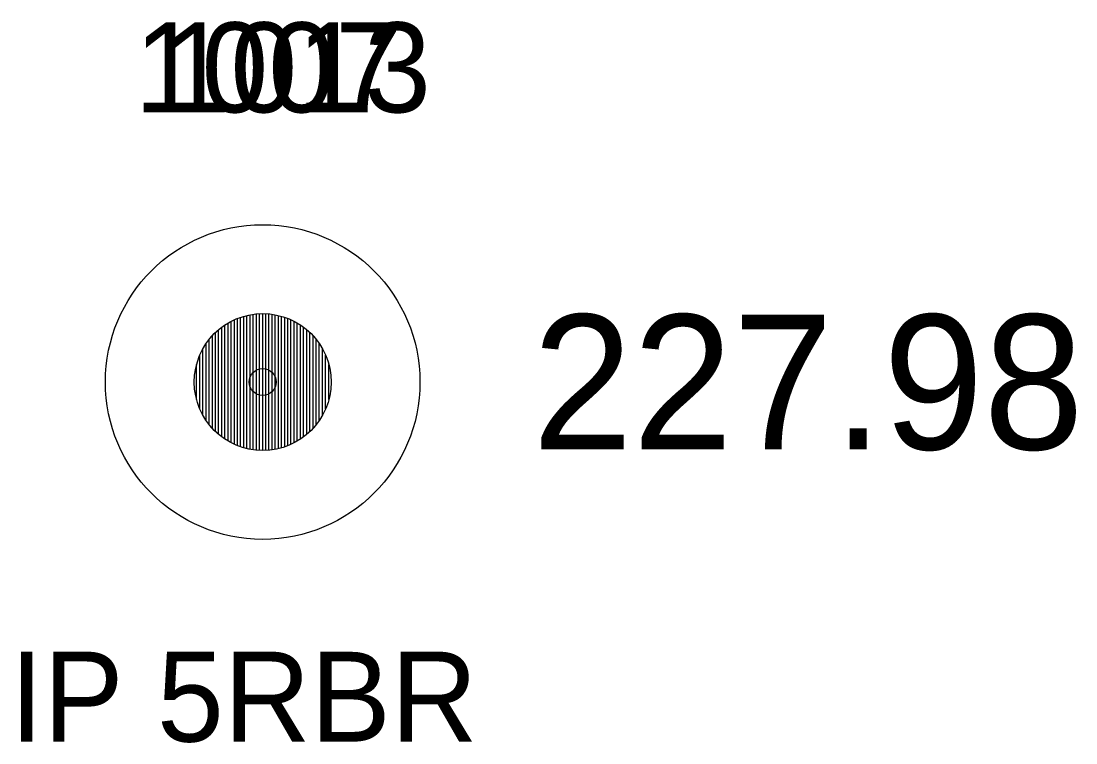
# Model space of a CAD drawing. Extents: x 1961231 to 1962574, y 799865 to 801120.
# Drawn here: x 1962434.89 to 1962446.63, y 799889.64 to 799897.66 of the extents above; entities that cross this region are included whole.
import ezdxf

# ---------------------------------------------------------------- set-up
doc = ezdxf.new("R2010")
doc.units = 0
for name, color, linetype in [('RD_EX_DV_Prop_txCode', 7, 'Continuous'), ('RD_EX_DV_PropPin', 7, 'Continuous'), ('RD_EX_TX_DV_Prop_ELEV', 7, 'Continuous'), ('RD_SMD_Locator', 7, 'Continuous')]:
    doc.layers.add(name, color=color, linetype=linetype)

msp = doc.modelspace()

# ---------------------------------------------------------------- linework, layer by layer
at = {"layer": 'RD_EX_DV_PropPin'}
for p, q in [((1962437.229, 799892.974), (1962437.229, 799894.326)), ((1962437.229, 799892.974), (1962437.229, 799894.326)), ((1962437.264, 799892.957), (1962437.264, 799894.343)), ((1962437.264, 799892.957), (1962437.264, 799894.343)), ((1962437.299, 799892.942), (1962437.299, 799894.358)), ((1962437.299, 799892.942), (1962437.299, 799894.358)), ((1962437.334, 799892.93), (1962437.334, 799894.37)), ((1962437.334, 799892.93), (1962437.334, 799894.37)), ((1962437.369, 799892.919), (1962437.369, 799894.381)), ((1962437.369, 799892.919), (1962437.369, 799894.381)), ((1962437.404, 799892.909), (1962437.404, 799894.391)), ((1962437.404, 799892.909), (1962437.404, 799894.391)), ((1962437.439, 799892.902), (1962437.439, 799894.398)), ((1962437.439, 799892.902), (1962437.439, 799894.398)), ((1962437.474, 799892.896), (1962437.474, 799894.404)), ((1962437.474, 799892.896), (1962437.474, 799894.404)), ((1962437.509, 799892.892), (1962437.509, 799894.408)), ((1962437.509, 799892.892), (1962437.509, 799894.408)), ((1962437.544, 799892.89), (1962437.544, 799894.41)), ((1962437.544, 799892.89), (1962437.544, 799894.41)), ((1962437.579, 799892.889), (1962437.579, 799894.411)), ((1962437.579, 799892.889), (1962437.579, 799894.411)), ((1962437.614, 799892.89), (1962437.614, 799894.41)), ((1962437.614, 799892.89), (1962437.614, 799894.41)), ((1962437.649, 799892.892), (1962437.649, 799894.408)), ((1962437.649, 799892.892), (1962437.649, 799894.408)), ((1962437.684, 799892.896), (1962437.684, 799894.404)), ((1962437.684, 799892.896), (1962437.684, 799894.404)), ((1962437.719, 799892.902), (1962437.719, 799894.398)), ((1962437.719, 799892.902), (1962437.719, 799894.398)), ((1962437.754, 799892.909), (1962437.754, 799894.391)), ((1962437.754, 799892.909), (1962437.754, 799894.391)), ((1962437.789, 799892.919), (1962437.789, 799894.381)), ((1962437.789, 799892.919), (1962437.789, 799894.381)), ((1962437.824, 799892.93), (1962437.824, 799894.37)), ((1962437.824, 799892.93), (1962437.824, 799894.37)), ((1962437.859, 799892.942), (1962437.859, 799894.358)), ((1962437.859, 799892.942), (1962437.859, 799894.358)), ((1962437.894, 799892.957), (1962437.894, 799894.343)), ((1962437.894, 799892.957), (1962437.894, 799894.343)), ((1962437.929, 799892.974), (1962437.929, 799894.326)), ((1962437.929, 799892.974), (1962437.929, 799894.326)), ((1962437.089, 799893.068), (1962437.089, 799894.232)), ((1962437.089, 799893.068), (1962437.089, 799894.232)), ((1962437.124, 799893.04), (1962437.124, 799894.26)), ((1962437.124, 799893.04), (1962437.124, 799894.26)), ((1962437.159, 799893.015), (1962437.159, 799894.285)), ((1962437.159, 799893.015), (1962437.159, 799894.285)), ((1962437.194, 799892.994), (1962437.194, 799894.306)), ((1962437.194, 799892.994), (1962437.194, 799894.306)), ((1962437.964, 799892.994), (1962437.964, 799894.306)), ((1962437.964, 799892.994), (1962437.964, 799894.306)), ((1962437.999, 799893.015), (1962437.999, 799894.285)), ((1962437.999, 799893.015), (1962437.999, 799894.285)), ((1962438.034, 799893.04), (1962438.034, 799894.26)), ((1962438.034, 799893.04), (1962438.034, 799894.26)), ((1962438.069, 799893.068), (1962438.069, 799894.232)), ((1962438.069, 799893.068), (1962438.069, 799894.232)), ((1962436.984, 799893.176), (1962436.984, 799894.124)), ((1962436.984, 799893.176), (1962436.984, 799894.124)), ((1962437.019, 799893.135), (1962437.019, 799894.165)), ((1962437.019, 799893.135), (1962437.019, 799894.165)), ((1962437.054, 799893.099), (1962437.054, 799894.201)), ((1962437.054, 799893.099), (1962437.054, 799894.201)), ((1962438.104, 799893.099), (1962438.104, 799894.201)), ((1962438.104, 799893.099), (1962438.104, 799894.201)), ((1962438.139, 799893.135), (1962438.139, 799894.165)), ((1962438.139, 799893.135), (1962438.139, 799894.165)), ((1962438.174, 799893.176), (1962438.174, 799894.124)), ((1962438.174, 799893.176), (1962438.174, 799894.124)), ((1962436.914, 799893.28), (1962436.914, 799894.02)), ((1962436.914, 799893.28), (1962436.914, 799894.02)), ((1962436.949, 799893.223), (1962436.949, 799894.077)), ((1962436.949, 799893.223), (1962436.949, 799894.077)), ((1962438.209, 799893.223), (1962438.209, 799894.077)), ((1962438.209, 799893.223), (1962438.209, 799894.077)), ((1962438.244, 799893.28), (1962438.244, 799894.02)), ((1962438.244, 799893.28), (1962438.244, 799894.02)), ((1962436.878, 799893.352), (1962436.878, 799893.948)), ((1962436.878, 799893.352), (1962436.878, 799893.948)), ((1962438.279, 799893.352), (1962438.279, 799893.948)), ((1962438.279, 799893.352), (1962438.279, 799893.948)), ((1962436.843, 799893.454), (1962436.843, 799893.846)), ((1962436.843, 799893.454), (1962436.843, 799893.846)), ((1962438.314, 799893.454), (1962438.314, 799893.846)), ((1962438.314, 799893.454), (1962438.314, 799893.846))]:
    msp.add_line(p, q, dxfattribs=at)
for radius in [1.75, 1.75, 0.761, 0.761]:
    msp.add_circle((1962437.579, 799893.65), radius, dxfattribs=at)
at = {"layer": 'RD_SMD_Locator'}
msp.add_circle((1962437.579, 799893.65), 0.15, dxfattribs=at)
msp.add_circle((1962437.579, 799893.65), 0.15, dxfattribs=at)

# ---------------------------------------------------------------- texts
at = {"layer": 'RD_EX_DV_Prop_txCode'}
for s, p in [('1007', (1962436.154, 799896.65)), ('1013', (1962436.476, 799896.65)), ('IP 5RBR', (1962434.768, 799889.65)), ('IP 5RBR', (1962434.768, 799889.65))]:
    msp.add_text(s, height=1, dxfattribs=at).set_placement(p)
at = {"layer": 'RD_EX_TX_DV_Prop_ELEV'}
msp.add_text('227.98', height=1.5, dxfattribs=at).set_placement((1962440.579, 799892.9))
msp.add_text('227.98', height=1.5, dxfattribs=at).set_placement((1962440.579, 799892.9))

doc.saveas('drawing.dxf')
